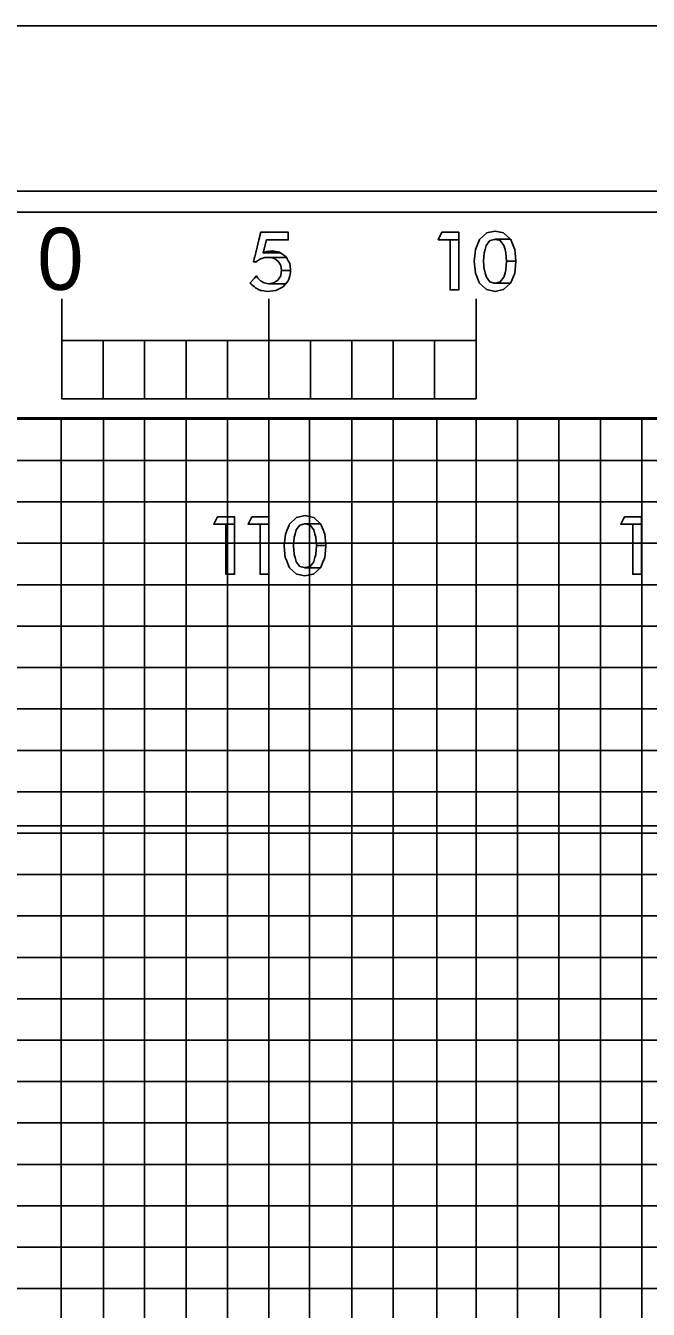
# Model space of a CAD drawing. Extents: x -13 to 323, y -5 to 1431.
# Drawn here: x 264.13 to 279.16, y 183.5 to 214.5 of the extents above; entities that cross this region are included whole.
import ezdxf

# ---------------------------------------------------------------- set-up
doc = ezdxf.new("R2010")
doc.units = 0
for name, color, linetype in [('Prop XS Bar Scale Labels', 7, 'Continuous'), ('Prop XS Offset Labels', 7, 'Continuous'), ('Scratch_Level_3', 7, 'Continuous'), ('Sheet Cross Section CELL', 7, 'Continuous'), ('Sheet Cross Section Grid Major CELL', 7, 'Continuous'), ('Sheet Cross Section Grid Middle CELL', 7, 'Continuous'), ('Sheet Cross Section Grid Minor 1 CELL', 7, 'Continuous'), ('Sheet Cross Section Grid Minor 2 CELL', 7, 'Continuous'), ('Sheet Cross Section Scale CELL', 7, 'Continuous'), ('Sheet Cutting Line CELL', 7, 'Continuous'), ('Sheet DOT Grid CELL', 7, 'Continuous'), ('Sheet Plot Border Inside CELL', 7, 'Continuous'), ('Sheet Plot Border Outside CELL', 7, 'Continuous')]:
    doc.layers.add(name, color=color, linetype=linetype)

msp = doc.modelspace()

# ---------------------------------------------------------------- linework, layer by layer
at = {"layer": 'Prop XS Bar Scale Labels'}
for points in [[(269.63, 208.81), (269.627, 208.798), (269.698, 208.798), (269.711, 208.81), (269.727, 208.824), (269.798, 208.867), (269.83, 208.877), (269.9, 208.899), (270.014, 208.905), (270.422, 208.905), (270.414, 208.92), (270.28, 209.015), (269.858, 209.015), (269.861, 209.028), (269.861, 209.028), (269.866, 209.048), (269.941, 209.326), (270.466, 209.326), (270.466, 209.511), (269.803, 209.511), (269.757, 209.326), (269.689, 209.048), (269.684, 209.028), (269.681, 209.015), (269.658, 208.92), (269.654, 208.905), (269.652, 208.899), (269.647, 208.877), (269.644, 208.867), (269.634, 208.824)], [(274.174, 209.511), (274.085, 209.329), (274.583, 209.329), (274.583, 209.511)], [(274.374, 209.329), (274.374, 208.12), (274.583, 208.12), (274.583, 209.329)], [(275.258, 208.125), (275.457, 208.084), (275.652, 208.125), (275.663, 208.127), (275.828, 208.279), (275.454, 208.279), (275.445, 208.281), (275.44, 208.283), (275.335, 208.312), (275.248, 208.425), (275.248, 208.426), (275.248, 208.426), (275.22, 208.527), (275.22, 208.529), (275.2, 208.602), (275.198, 208.606), (275.181, 208.809), (275.181, 208.811), (275.181, 208.813), (275.198, 209.015), (275.219, 209.092), (275.22, 209.094), (275.246, 209.192), (275.247, 209.195), (275.335, 209.31), (275.448, 209.339), (275.452, 209.34), (275.462, 209.343), (275.832, 209.343), (275.669, 209.492), (275.66, 209.494), (275.46, 209.538), (275.46, 209.538), (275.252, 209.494), (275.25, 209.492), (275.088, 209.343), (275.085, 209.34), (275.084, 209.339), (275.072, 209.31), (275.025, 209.195), (275.024, 209.192), (274.983, 209.094), (274.983, 209.092), (274.975, 209.015), (274.954, 208.813), (274.953, 208.811), (274.954, 208.809), (274.974, 208.606), (274.974, 208.602), (274.982, 208.529), (274.982, 208.527), (275.023, 208.426), (275.024, 208.425), (275.07, 208.312), (275.082, 208.283), (275.082, 208.281), (275.085, 208.279), (275.255, 208.127)], [(275.719, 209.015), (275.735, 208.813), (275.962, 208.813), (275.942, 209.015), (275.935, 209.092), (275.934, 209.094), (275.934, 209.094), (275.895, 209.192), (275.895, 209.192), (275.893, 209.195), (275.848, 209.31), (275.847, 209.31), (275.835, 209.339), (275.835, 209.34), (275.832, 209.343), (275.462, 209.343), (275.472, 209.34), (275.475, 209.339), (275.582, 209.31), (275.669, 209.195), (275.672, 209.192), (275.698, 209.094), (275.698, 209.092)], [(269.895, 209.028), (269.858, 209.015), (270.28, 209.015), (270.262, 209.028), (270.164, 209.048), (269.953, 209.048)], [(270.091, 209.062), (269.953, 209.048), (270.164, 209.048), (270.091, 209.062)], [(269.627, 208.798), (269.685, 208.786), (269.698, 208.798)], [(270.286, 208.711), (270.308, 208.591), (270.521, 208.591), (270.51, 208.711), (270.51, 208.711), (270.507, 208.751), (270.487, 208.786), (270.481, 208.798), (270.475, 208.81), (270.467, 208.824), (270.443, 208.867), (270.438, 208.877), (270.426, 208.899), (270.422, 208.905), (270.014, 208.905), (270.041, 208.899), (270.132, 208.877), (270.146, 208.867), (270.206, 208.824), (270.227, 208.81), (270.234, 208.798), (270.241, 208.786), (270.262, 208.751)], [(275.465, 208.281), (275.454, 208.279), (275.828, 208.279), (275.831, 208.281), (275.833, 208.283), (275.845, 208.312), (275.892, 208.425), (275.892, 208.426), (275.934, 208.527), (275.935, 208.529), (275.942, 208.602), (275.942, 208.606), (275.962, 208.809), (275.963, 208.811), (275.962, 208.813), (275.735, 208.813), (275.735, 208.811), (275.735, 208.809), (275.719, 208.606), (275.718, 208.602), (275.699, 208.529), (275.698, 208.527), (275.671, 208.426), (275.67, 208.425), (275.582, 208.312), (275.47, 208.283)], [(269.829, 208.103), (269.965, 208.084), (270.163, 208.103), (270.171, 208.107), (270.294, 208.167), (270.294, 208.167), (270.344, 208.191), (270.388, 208.245), (270.408, 208.269), (269.996, 208.269), (269.887, 208.288), (269.885, 208.289), (269.882, 208.29), (269.799, 208.336), (269.789, 208.347), (269.783, 208.353), (269.783, 208.353), (269.733, 208.405), (269.7, 208.455), (269.7, 208.455), (269.655, 208.405), (269.608, 208.353), (269.602, 208.347), (269.593, 208.336), (269.551, 208.29), (269.55, 208.289), (269.551, 208.288), (269.566, 208.269), (269.585, 208.245), (269.649, 208.191), (269.677, 208.167), (269.801, 208.107)], [(270.103, 208.288), (269.996, 208.269), (270.408, 208.269), (270.423, 208.288), (270.424, 208.289), (270.425, 208.29), (270.425, 208.29), (270.462, 208.336), (270.471, 208.347), (270.473, 208.353), (270.487, 208.405), (270.502, 208.46), (270.525, 208.544), (270.521, 208.591), (270.308, 208.591), (270.3, 208.544), (270.286, 208.46), (270.25, 208.405), (270.217, 208.353), (270.207, 208.347), (270.19, 208.336), (270.116, 208.29), (270.108, 208.289)]]:
    msp.add_lwpolyline(points, close=True, dxfattribs=at)
at = {"layer": 'Prop XS Offset Labels'}
for points in [[(268.76, 202.641), (268.671, 202.459), (269.17, 202.459), (269.17, 202.641)], [(268.961, 202.459), (268.961, 201.25), (269.17, 201.25), (269.17, 202.459)], [(269.587, 202.641), (269.498, 202.459), (269.997, 202.459), (269.997, 202.641)], [(269.788, 202.459), (269.788, 201.25), (269.997, 201.25), (269.997, 202.459)], [(270.672, 201.255), (270.871, 201.214), (271.066, 201.255), (271.077, 201.257), (271.242, 201.409), (270.868, 201.409), (270.858, 201.411), (270.853, 201.413), (270.749, 201.442), (270.662, 201.555), (270.661, 201.556), (270.661, 201.556), (270.634, 201.657), (270.633, 201.659), (270.613, 201.732), (270.612, 201.736), (270.594, 201.939), (270.594, 201.941), (270.595, 201.943), (270.612, 202.145), (270.633, 202.222), (270.633, 202.224), (270.66, 202.322), (270.661, 202.325), (270.749, 202.44), (270.862, 202.469), (270.865, 202.47), (270.876, 202.473), (271.246, 202.473), (271.082, 202.622), (271.074, 202.624), (270.873, 202.668), (270.873, 202.668), (270.665, 202.624), (270.663, 202.622), (270.502, 202.473), (270.499, 202.47), (270.498, 202.469), (270.486, 202.44), (270.439, 202.325), (270.437, 202.322), (270.397, 202.224), (270.397, 202.222), (270.389, 202.145), (270.367, 201.943), (270.367, 201.941), (270.367, 201.939), (270.387, 201.736), (270.388, 201.732), (270.395, 201.659), (270.396, 201.657), (270.437, 201.556), (270.437, 201.555), (270.483, 201.442), (270.495, 201.413), (270.496, 201.411), (270.499, 201.409), (270.669, 201.257)], [(271.132, 202.145), (271.149, 201.943), (271.376, 201.943), (271.356, 202.145), (271.349, 202.222), (271.348, 202.224), (271.348, 202.224), (271.308, 202.322), (271.308, 202.322), (271.307, 202.325), (271.261, 202.44), (271.261, 202.44), (271.249, 202.469), (271.249, 202.47), (271.246, 202.473), (270.876, 202.473), (270.885, 202.47), (270.889, 202.469), (270.995, 202.44), (271.083, 202.325), (271.085, 202.322), (271.111, 202.224), (271.112, 202.222)], [(278.581, 202.641), (278.492, 202.459), (278.99, 202.459), (278.99, 202.641)], [(278.781, 202.459), (278.781, 201.25), (278.99, 201.25), (278.99, 202.459)], [(270.878, 201.411), (270.868, 201.409), (271.242, 201.409), (271.245, 201.411), (271.247, 201.413), (271.259, 201.442), (271.305, 201.555), (271.306, 201.556), (271.348, 201.657), (271.348, 201.659), (271.355, 201.732), (271.356, 201.736), (271.376, 201.939), (271.376, 201.941), (271.376, 201.943), (271.149, 201.943), (271.149, 201.941), (271.148, 201.939), (271.132, 201.736), (271.132, 201.732), (271.112, 201.659), (271.112, 201.657), (271.085, 201.556), (271.084, 201.555), (270.995, 201.442), (270.883, 201.413)]]:
    msp.add_lwpolyline(points, close=True, dxfattribs=at)
at = {"layer": 'Scratch_Level_3'}
msp.add_lwpolyline([(20, 195.176), (300, 195.176), (300, 165.176), (20, 165.176)], close=True, dxfattribs=at)
at = {"layer": 'Sheet Cross Section CELL'}
for points in [[(320, 210), (0, 210), (0, 0), (320, 0)], [(280, 210), (260, 210), (260, 205.03), (280, 205.03)]]:
    msp.add_lwpolyline(points, close=True, dxfattribs=at)
at = {"layer": 'Sheet Cross Section Grid Major CELL'}
msp.add_line((270, 0), (270, 205), dxfattribs=at)
msp.add_lwpolyline([(0, 200), (320, 200), (320, 190), (0, 190)], dxfattribs=at)
at = {"layer": 'Sheet Cross Section Grid Middle CELL'}
for points in [[(255, 0), (255, 210), (259.93, 210), (260, 210), (260, 205), (264.99, 205), (264.99, 0)], [(0, 205), (275, 205)], [(275, 0), (275, 205), (285, 205), (285, 0)], [(0, 185), (320, 185), (320, 195), (0, 195)]]:
    msp.add_lwpolyline(points, dxfattribs=at)
at = {"layer": 'Sheet Cross Section Grid Minor 1 CELL'}
msp.add_line((0, 204), (320, 204), dxfattribs=at)
for points in [[(0, 203), (270, 203), (320, 203), (320, 202), (0, 202)], [(0, 201), (320, 201), (320, 199), (0, 199)], [(0, 198), (320, 198), (320, 197), (0, 196.98)], [(0, 196), (320, 196), (320, 194), (0, 194)], [(0, 193), (320, 193), (320, 192), (0, 192)], [(0, 191), (320, 191), (320, 189), (0, 189)], [(0, 188), (320, 188), (320, 187), (0, 187)], [(0, 186), (320, 186), (320, 184), (0, 184)]]:
    msp.add_lwpolyline(points, dxfattribs=at)
at = {"layer": 'Sheet Cross Section Grid Minor 2 CELL'}
for p, q in [((267, 205), (266.01, 205)), ((266.01, 205), (266.01, 0)), ((267, 0), (267, 205)), ((269, 205), (268, 205)), ((268, 205), (268, 0)), ((269, 0), (269, 205))]:
    msp.add_line(p, q, dxfattribs=at)
for points in [[(270, 0), (270.98, 0), (270.98, 205), (272, 205), (272, 0)], [(272, 0), (273, 0), (273, 205), (274.05, 205), (274.05, 0)], [(275, 0), (276, 0), (276, 205), (277, 205), (277, 0)], [(277, 0), (278, 0), (278, 205), (279, 205), (279, 0)]]:
    msp.add_lwpolyline(points, dxfattribs=at)
at = {"layer": 'Sheet Cross Section Scale CELL'}
for p, q in [((265, 205.49), (265, 207.9)), ((265, 206.9), (265, 207.9)), ((270, 205.49), (270, 207.9)), ((275, 205.49), (275, 207.9)), ((275, 206.9), (275, 207.9))]:
    msp.add_line(p, q, dxfattribs=at)
for points in [[(275, 206.9), (265, 206.9), (265, 205.49), (275, 205.49)], [(265, 206.9), (266, 206.9), (266, 205.49), (265, 205.49)], [(267, 206.9), (268, 206.9), (268, 205.49), (267, 205.49)], [(269, 206.9), (270, 206.9), (270, 205.49), (269, 205.49)], [(271, 206.9), (272, 206.9), (272, 205.49), (271, 205.49)], [(273, 206.9), (274, 206.9), (274, 205.49), (273, 205.49)]]:
    msp.add_lwpolyline(points, close=True, dxfattribs=at)
at = {"layer": 'Sheet Cutting Line CELL'}
msp.add_line((323.3, 214.5), (-13.4, 214.5), dxfattribs=at)
at = {"layer": 'Sheet DOT Grid CELL'}
for p, q in [((270, 0), (270, 204.687)), ((0, 200), (320, 200)), ((0, 190), (320, 190))]:
    msp.add_line(p, q, dxfattribs=at)
at = {"layer": 'Sheet Plot Border Inside CELL'}
msp.add_lwpolyline([(-10.8, -0.5), (322.4, -0.5), (322.4, 210.5), (-10.8, 210.5)], close=True, dxfattribs=at)
at = {"layer": 'Sheet Plot Border Outside CELL'}
msp.add_lwpolyline([(-13.4, -4.5), (323.3, -4.5), (323.3, 214.5), (-13.4, 214.5)], close=True, dxfattribs=at)

# ---------------------------------------------------------------- texts
at = {"layer": 'Sheet Cross Section Scale CELL'}
msp.add_text('0', height=1.5, dxfattribs=at).set_placement((264.41, 208.12))

doc.saveas('drawing.dxf')
